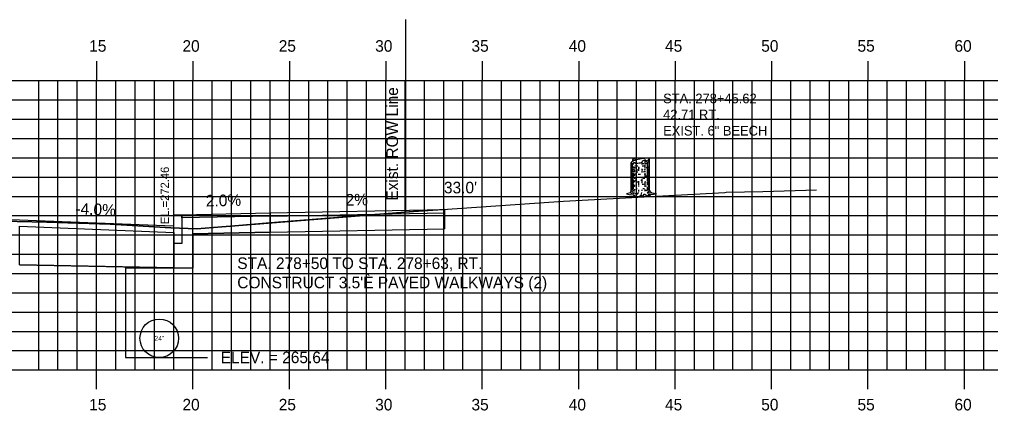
# Model space of a CAD drawing. Extents: x 854676 to 854846, y 366268 to 366378.
# Drawn here: x 854770.1 to 854820.5, y 366300.1 to 366320.4 of the extents above; entities that cross this region are included whole.
import ezdxf

# ---------------------------------------------------------------- set-up
doc = ezdxf.new("R2010")
doc.units = 0
for name, color, linetype in [('ANNOTATION', 7, 'Continuous'), ('D_Curb_Type_1_Rt', 7, 'Continuous'), ('D_Roadway_Edge_Shoulder', 7, 'Continuous'), ('D_Roadway_Sidewalks_Paved', 7, 'Continuous'), ('D_Roadway_SubGrade', 7, 'Continuous'), ('D_Text_Monospaced', 7, 'Continuous'), ('D_Text_Standard', 7, 'Continuous'), ('E_ROW_Line', 7, 'Continuous'), ('H_V ANNOTATION', 7, 'Continuous'), ('JUNK COM EXC', 7, 'Continuous'), ('junk strct exc', 7, 'Continuous'), ('MAJOR', 7, 'Continuous'), ('MINOR', 7, 'Continuous'), ('PDRAIN', 7, 'Continuous'), ('S_Roadway_Centerline', 7, 'Continuous'), ('S_Trees_Decid_NonPay', 7, 'Continuous')]:
    doc.layers.add(name, color=color, linetype=linetype)

msp = doc.modelspace()

# ---------------------------------------------------------------- linework, layer by layer
at = {"layer": 'D_Curb_Type_1_Rt'}
msp.add_lwpolyline([(854778.523, 366310.284), (854778.523, 366308.784), (854778.106, 366308.784), (854778.106, 366310.284)], close=True, dxfattribs=at)
at = {"layer": 'D_Roadway_Edge_Shoulder'}
msp.add_lwpolyline([(854740.106, 366309.92), (854748.106, 366310.24), (854759.106, 366310.24), (854770.106, 366310.02), (854778.103, 366309.701)], dxfattribs=at)
at = {"layer": 'D_Roadway_Sidewalks_Paved'}
msp.add_line((854783.115, 366310.209), (854792.151, 366310.39), dxfattribs=at)
msp.add_lwpolyline([(854783.111, 366310.375), (854792.151, 366310.556)], dxfattribs=at)
msp.add_lwpolyline([(854778.523, 366310.283), (854783.111, 366310.375), (854783.111, 366310.208), (854778.523, 366310.116)], close=True, dxfattribs=at)
at = {"layer": 'D_Roadway_SubGrade'}
for p in [(854792.151, 366310.556), (854783.112, 366309.375)]:
    msp.add_line(p, (854792.151, 366309.556), dxfattribs=at)
msp.add_lwpolyline([(854783.112, 366310.208), (854783.112, 366309.375), (854779.106, 366309.295), (854779.106, 366307.507), (854778.106, 366307.527)], dxfattribs=at)
msp.add_lwpolyline([(854770.106, 366309.687), (854778.106, 366309.367), (854778.106, 366307.527), (854770.106, 366307.687)], close=True, dxfattribs=at)
at = {"layer": 'D_Text_Standard'}
msp.add_lwpolyline([(854779.106, 366302.876), (854779.182, 366302.886), (854779.862, 366302.886)], dxfattribs=at)
at = {"layer": 'E_ROW_Line'}
msp.add_line((854790.137, 366310.411), (854790.137, 366320.411), dxfattribs=at)
at = {"layer": 'JUNK COM EXC'}
for points in [[(854783.112, 366309.858), (854783.112, 366309.375), (854792.151, 366309.556), (854792.151, 366310.556), (854790.546, 366310.443), (854783.112, 366309.858)], [(854770.106, 366307.687), (854779.106, 366307.507), (854779.106, 366309.295), (854783.112, 366309.375), (854783.111, 366309.858), (854781.269, 366309.713), (854780.594, 366309.653), (854779.299, 366309.553), (854777.965, 366309.609), (854774.811, 366309.794), (854771.526, 366309.892), (854768.432, 366309.965)]]:
    msp.add_lwpolyline(points, dxfattribs=at)
at = {"layer": 'junk strct exc'}
msp.add_lwpolyline([(854775.606, 366307.507), (854775.606, 366302.876), (854779.106, 366302.876), (854779.106, 366307.507)], close=True, dxfattribs=at)
at = {"layer": 'MAJOR'}
for p, q in [((854774.106, 366318.238), (854774.106, 366317.236)), ((854779.106, 366318.238), (854779.106, 366317.236)), ((854784.106, 366318.238), (854784.106, 366317.236)), ((854789.106, 366318.238), (854789.106, 366317.236)), ((854794.106, 366318.238), (854794.106, 366317.236)), ((854799.106, 366318.238), (854799.106, 366317.236)), ((854804.106, 366318.238), (854804.106, 366317.236)), ((854809.106, 366318.238), (854809.106, 366317.236)), ((854814.106, 366318.238), (854814.106, 366317.236)), ((854819.106, 366318.238), (854819.106, 366317.236)), ((854689.106, 366317.236), (854829.106, 366317.236)), ((854689.106, 366317.236), (854829.106, 366317.236)), ((854774.106, 366302.236), (854774.106, 366317.236)), ((854779.106, 366302.236), (854779.106, 366317.236)), ((854784.106, 366302.236), (854784.106, 366317.236)), ((854789.106, 366302.236), (854789.106, 366317.236)), ((854794.106, 366302.236), (854794.106, 366317.236)), ((854799.106, 366302.236), (854799.106, 366317.236)), ((854804.106, 366302.236), (854804.106, 366317.236)), ((854809.106, 366302.236), (854809.106, 366317.236)), ((854814.106, 366302.236), (854814.106, 366317.236)), ((854819.106, 366302.236), (854819.106, 366317.236)), ((854689.106, 366312.236), (854829.106, 366312.236)), ((854689.106, 366307.236), (854829.106, 366307.236)), ((854689.106, 366302.236), (854829.106, 366302.236)), ((854689.106, 366302.236), (854829.106, 366302.236)), ((854774.106, 366301.234), (854774.106, 366302.236)), ((854779.106, 366301.234), (854779.106, 366302.236)), ((854784.106, 366301.234), (854784.106, 366302.236)), ((854789.106, 366301.234), (854789.106, 366302.236)), ((854794.106, 366301.234), (854794.106, 366302.236)), ((854799.106, 366301.234), (854799.106, 366302.236)), ((854804.106, 366301.234), (854804.106, 366302.236)), ((854809.106, 366301.234), (854809.106, 366302.236)), ((854814.106, 366301.234), (854814.106, 366302.236)), ((854819.106, 366301.234), (854819.106, 366302.236))]:
    msp.add_line(p, q, dxfattribs=at)
at = {"layer": 'MINOR'}
for p, q in [((854771.106, 366302.236), (854771.106, 366317.236)), ((854772.106, 366302.236), (854772.106, 366317.236)), ((854773.106, 366302.236), (854773.106, 366317.236)), ((854775.106, 366302.236), (854775.106, 366317.236)), ((854776.106, 366302.236), (854776.106, 366317.236)), ((854777.106, 366302.236), (854777.106, 366317.236)), ((854778.106, 366302.236), (854778.106, 366317.236)), ((854780.106, 366302.236), (854780.106, 366317.236)), ((854781.106, 366302.236), (854781.106, 366317.236)), ((854782.106, 366302.236), (854782.106, 366317.236)), ((854783.106, 366302.236), (854783.106, 366317.236)), ((854785.106, 366302.236), (854785.106, 366317.236)), ((854786.106, 366302.236), (854786.106, 366317.236)), ((854787.106, 366302.236), (854787.106, 366317.236)), ((854788.106, 366302.236), (854788.106, 366317.236)), ((854790.106, 366302.236), (854790.106, 366317.236)), ((854791.106, 366302.236), (854791.106, 366317.236)), ((854792.106, 366302.236), (854792.106, 366317.236)), ((854793.106, 366302.236), (854793.106, 366317.236)), ((854795.106, 366302.236), (854795.106, 366317.236)), ((854796.106, 366302.236), (854796.106, 366317.236)), ((854797.106, 366302.236), (854797.106, 366317.236)), ((854798.106, 366302.236), (854798.106, 366317.236)), ((854800.106, 366302.236), (854800.106, 366317.236)), ((854801.106, 366302.236), (854801.106, 366317.236)), ((854802.106, 366302.236), (854802.106, 366317.236)), ((854803.106, 366302.236), (854803.106, 366317.236)), ((854805.106, 366302.236), (854805.106, 366317.236)), ((854806.106, 366302.236), (854806.106, 366317.236)), ((854807.106, 366302.236), (854807.106, 366317.236)), ((854808.106, 366302.236), (854808.106, 366317.236)), ((854810.106, 366302.236), (854810.106, 366317.236)), ((854811.106, 366302.236), (854811.106, 366317.236)), ((854812.106, 366302.236), (854812.106, 366317.236)), ((854813.106, 366302.236), (854813.106, 366317.236)), ((854815.106, 366302.236), (854815.106, 366317.236)), ((854816.106, 366302.236), (854816.106, 366317.236)), ((854817.106, 366302.236), (854817.106, 366317.236)), ((854818.106, 366302.236), (854818.106, 366317.236)), ((854820.106, 366302.236), (854820.106, 366317.236)), ((854689.106, 366316.236), (854829.106, 366316.236)), ((854689.106, 366315.236), (854829.106, 366315.236)), ((854689.106, 366314.236), (854829.106, 366314.236)), ((854689.106, 366313.236), (854829.106, 366313.236)), ((854689.106, 366311.236), (854829.106, 366311.236)), ((854689.106, 366310.236), (854829.106, 366310.236)), ((854689.106, 366309.236), (854829.106, 366309.236)), ((854689.106, 366308.236), (854829.106, 366308.236)), ((854689.106, 366306.236), (854829.106, 366306.236)), ((854689.106, 366305.236), (854829.106, 366305.236)), ((854689.106, 366304.236), (854829.106, 366304.236)), ((854689.106, 366303.236), (854829.106, 366303.236))]:
    msp.add_line(p, q, dxfattribs=at)
at = {"layer": 'PDRAIN'}
msp.add_lwpolyline([(854775.606, 366307.577), (854775.606, 366302.876), (854779.106, 366302.876), (854779.106, 366307.507)], dxfattribs=at)
msp.add_circle((854777.356, 366303.876), 1, dxfattribs=at)
at = {"layer": 'S_Roadway_Centerline'}
msp.add_lwpolyline([(854768.432, 366309.965), (854771.526, 366309.892), (854774.811, 366309.794), (854777.965, 366309.609), (854779.299, 366309.553), (854780.594, 366309.653), (854781.269, 366309.713), (854790.546, 366310.443), (854798.319, 366310.991), (854806.682, 366311.444), (854806.754, 366311.454), (854808.651, 366311.486), (854811.433, 366311.566)], dxfattribs=at)
at = {"layer": 'S_Trees_Decid_NonPay'}
for p, q in [((854801.886, 366312.941), (854801.886, 366312.723)), ((854801.928, 366312.936), (854801.928, 366312.884)), ((854802.086, 366312.946), (854802.086, 366312.867)), ((854802.383, 366312.999), (854802.383, 366312.892)), ((854802.53, 366313.044), (854802.53, 366312.896)), ((854802.649, 366313.027), (854802.649, 366312.727)), ((854802.717, 366313.114), (854802.717, 366313.02)), ((854801.859, 366312.871), (854801.859, 366312.789)), ((854801.859, 366312.719), (854801.859, 366312.589)), ((854801.859, 366312.567), (854801.859, 366312.385)), ((854801.886, 366312.654), (854801.886, 366312.502)), ((854801.928, 366312.781), (854801.928, 366312.698)), ((854801.928, 366312.663), (854801.928, 366312.589)), ((854801.928, 366312.562), (854801.928, 366312.502)), ((854801.928, 366312.449), (854801.928, 366312.268)), ((854801.999, 366312.762), (854801.999, 366312.676)), ((854801.999, 366312.605), (854801.999, 366312.484)), ((854801.999, 366312.409), (854801.999, 366312.294)), ((854802.086, 366312.781), (854802.086, 366312.696)), ((854802.086, 366312.585), (854802.086, 366312.484)), ((854802.203, 366312.762), (854802.203, 366312.562)), ((854802.383, 366312.663), (854802.383, 366312.577)), ((854802.383, 366312.542), (854802.383, 366312.472)), ((854802.53, 366312.848), (854802.53, 366312.68)), ((854802.649, 366312.698), (854802.649, 366312.567)), ((854802.649, 366312.533), (854802.649, 366312.252)), ((854802.717, 366312.793), (854802.717, 366312.71)), ((854802.717, 366312.641), (854802.717, 366312.39)), ((854801.857, 366311.924), (854801.858, 366311.665)), ((854801.859, 366312.338), (854801.859, 366312.091)), ((854801.859, 366312.072), (854801.859, 366311.978)), ((854801.886, 366312.397), (854801.886, 366312.319)), ((854801.886, 366312.293), (854801.886, 366312.186)), ((854801.886, 366312.151), (854801.886, 366312.05)), ((854801.886, 366312.024), (854801.886, 366311.842)), ((854801.928, 366312.237), (854801.928, 366312.155)), ((854801.928, 366312.101), (854801.928, 366311.93)), ((854801.928, 366311.897), (854801.928, 366311.617)), ((854801.999, 366312.233), (854801.999, 366312.151)), ((854801.999, 366312.064), (854801.999, 366311.967)), ((854802.086, 366312.399), (854802.086, 366312.323)), ((854802.086, 366312.138), (854802.086, 366312.041)), ((854802.203, 366312.025), (854802.203, 366311.838)), ((854802.383, 366312.138), (854802.383, 366311.916)), ((854802.53, 366312.373), (854802.53, 366312.225)), ((854802.53, 366311.955), (854802.53, 366311.802)), ((854802.649, 366312.182), (854802.649, 366312.037)), ((854802.649, 366311.967), (854802.649, 366311.825)), ((854802.717, 366312.307), (854802.717, 366312.077)), ((854802.717, 366312.006), (854802.717, 366311.846)), ((854801.806, 366311.378), (854801.873, 366311.409)), ((854801.888, 366311.5), (854801.853, 366311.449)), ((854801.859, 366311.626), (854801.859, 366311.552)), ((854801.886, 366311.739), (854801.886, 366311.547)), ((854801.928, 366311.565), (854801.928, 366311.539)), ((854801.999, 366311.838), (854801.999, 366311.739)), ((854801.999, 366311.609), (854801.999, 366311.551)), ((854802.086, 366311.716), (854802.086, 366311.492)), ((854802.203, 366311.807), (854802.203, 366311.754)), ((854802.203, 366311.578), (854802.203, 366311.487)), ((854802.343, 366311.296), (854802.378, 366311.442)), ((854802.383, 366311.583), (854802.383, 366311.516)), ((854802.53, 366311.59), (854802.53, 366311.512)), ((854802.649, 366311.724), (854802.649, 366311.543)), ((854802.649, 366311.483), (854802.691, 366311.387)), ((854802.717, 366311.829), (854802.717, 366311.724)), ((854802.717, 366311.688), (854802.717, 366311.564))]:
    msp.add_line(p, q, dxfattribs=at)
for points in [[(854801.817, 366312.978), (854801.817, 366311.566), (854801.795, 366311.418), (854801.592, 366311.375), (854801.731, 366311.339), (854801.95, 366311.321), (854802.019, 366311.277), (854801.898, 366311.189), (854802.229, 366311.232), (854802.343, 366311.296), (854802.435, 366311.236), (854802.491, 366311.315), (854802.483, 366311.352), (854802.544, 366311.354), (854802.596, 366311.296), (854802.828, 366311.245), (854802.701, 366311.333), (854802.833, 366311.335), (854803.141, 366311.373), (854802.903, 366311.403), (854802.825, 366311.461), (854802.786, 366311.583), (854802.769, 366311.936), (854802.769, 366313.17)], [(854801.912, 366313.059), (854801.916, 366313.153), (854801.931, 366313.126), (854801.931, 366313.248), (854801.952, 366313.184), (854801.966, 366313.217), (854801.983, 366313.161), (854801.999, 366313.178), (854802.017, 366313.17), (854802.036, 366313.103)], [(854801.935, 366312.935), (854801.952, 366312.997), (854801.974, 366312.985), (854802.005, 366313.02), (854802.038, 366312.941)], [(854802.405, 366313.004), (854802.413, 366313.071), (854802.437, 366313.075), (854802.446, 366313.11), (854802.477, 366313.096), (854802.491, 366313.11), (854802.515, 366313.087), (854802.538, 366313.096), (854802.551, 366313.145), (854802.559, 366313.102), (854802.59, 366313.11), (854802.593, 366313.059)], [(854801.857, 366311.426), (854801.935, 366311.409), (854801.952, 366311.366)], [(854801.935, 366311.409), (854801.979, 366311.444), (854801.987, 366311.492)], [(854802.083, 366311.444), (854802.077, 366311.375), (854802.014, 366311.362)], [(854802.195, 366311.438), (854802.195, 366311.401), (854802.143, 366311.371), (854802.126, 366311.321)], [(854802.72, 366311.521), (854802.728, 366311.444), (854802.806, 366311.395)]]:
    msp.add_lwpolyline(points, dxfattribs=at)
for centre, radius, start, end in [((854801.841, 366312.978), 0.0237, 161.8277, 175.7722), ((854801.836, 366312.978), 0.0179, 175.7722, 191.8277), ((854801.836, 366312.978), 0.0179, 191.8277, 207.8832), ((854801.837, 366312.909), 0.0191, 173.8872, 180), ((854801.837, 366312.909), 0.0191, 180, 196.0515), ((854801.851, 366312.975), 0.0336, 143.0514, 161.8277), ((854801.843, 366312.911), 0.0252, 196.0515, 210), ((854801.841, 366312.981), 0.0237, 207.8832, 221.8277), ((854801.848, 366312.988), 0.0336, 221.8277, 240.604), ((854801.899, 366312.939), 0.0935, 131.8277, 143.0514), ((854801.877, 366313.04), 0.0935, 240.604, 251.8277), ((854802.051, 366312.769), 0.322, 109.7098, 131.8277), ((854801.949, 366313.257), 0.322, 251.8277, 267.5521), ((854802.788, 366310.711), 2.507, 101.8277, 109.7098), ((854801.798, 366315.437), 2.507, 275.4987, 281.8277), ((854802.788, 366310.711), 2.507, 93.9457, 101.8277), ((854801.798, 366315.437), 2.507, 281.8277, 284.0013), ((854802.294, 366315.284), 2.356, 272.1614, 274.76), ((854802.294, 366315.284), 2.356, 276.7201, 278.1032), ((854801.798, 366315.437), 2.507, 288.4719, 289.7098), ((854802.637, 366312.891), 0.322, 71.8277, 93.9457), ((854802.58, 366313.274), 0.326, 278.1032, 282.1964), ((854802.535, 366313.38), 0.322, 289.7098, 311.8277), ((854802.58, 366313.274), 0.326, 291.6757, 300), ((854802.709, 366313.108), 0.0935, 60.604, 71.8277), ((854802.694, 366313.077), 0.0984, 300, 311.2506), ((854802.688, 366313.209), 0.0935, 311.8277, 323.0514), ((854802.738, 366313.161), 0.0336, 41.8277, 60.604), ((854802.735, 366313.029), 0.0356, 311.2506, 330), ((854802.735, 366313.173), 0.0336, 323.0514, 341.8277), ((854802.745, 366313.167), 0.0237, 27.8832, 41.8277), ((854802.751, 366313.17), 0.0179, 11.8277, 27.8832), ((854802.744, 366313.024), 0.0252, 330, 343.9485), ((854802.745, 366313.17), 0.0237, 341.8277, 355.7722), ((854802.751, 366313.17), 0.0179, 355.7722, 11.8277), ((854802.75, 366313.022), 0.0191, 0, 16.0515), ((854802.75, 366313.022), 0.0191, 343.9485, 0), ((854801.837, 366312.808), 0.0191, 173.8872, 180), ((854801.837, 366312.808), 0.0191, 180, 196.0515), ((854801.837, 366312.705), 0.0191, 173.8872, 180), ((854801.837, 366312.705), 0.0191, 180, 196.0515), ((854801.837, 366312.6), 0.0191, 173.8872, 180), ((854801.837, 366312.6), 0.0191, 180, 196.0515), ((854801.837, 366312.485), 0.0191, 173.8872, 180), ((854801.837, 366312.485), 0.0191, 180, 196.0515), ((854801.843, 366312.81), 0.0252, 196.0515, 210), ((854801.843, 366312.602), 0.0252, 196.0515, 210), ((854801.843, 366312.487), 0.0252, 196.0515, 210), ((854801.852, 366312.916), 0.0356, 210, 228.7494), ((854801.852, 366312.815), 0.0356, 210, 228.7494), ((854801.852, 366312.607), 0.0356, 210, 228.7494), ((854801.852, 366312.492), 0.0356, 210, 228.7494), ((854801.894, 366312.963), 0.0984, 228.7494, 240), ((854801.894, 366312.862), 0.0984, 228.7494, 240), ((854801.894, 366312.654), 0.0984, 228.7494, 240), ((854801.894, 366312.539), 0.0984, 228.7494, 240), ((854802.008, 366313.161), 0.326, 240, 248.0494), ((854802.008, 366313.06), 0.326, 240, 248.0494), ((854802.008, 366312.852), 0.326, 240, 248.0494), ((854802.008, 366312.737), 0.326, 240, 255.9618), ((854802.008, 366312.957), 0.326, 255.9618, 261.8968), ((854802.008, 366312.852), 0.326, 255.9618, 261.8968), ((854802.008, 366313.06), 0.326, 260.9146, 261.8968), ((854802.294, 366315.07), 2.356, 261.8968, 264.9353), ((854802.294, 366314.967), 2.356, 261.8968, 262.6162), ((854802.294, 366314.862), 2.356, 261.8968, 262.8132), ((854802.294, 366314.747), 2.356, 262.8132, 264.9353), ((854802.294, 366315.171), 2.356, 263.2266, 266.8519), ((854802.294, 366314.862), 2.356, 264.9353, 266.9933), ((854802.294, 366314.967), 2.356, 266.0259, 267.8019), ((854802.294, 366315.07), 2.356, 267.8019, 269.1881), ((854802.294, 366314.967), 2.356, 272.1614, 273.4964), ((854802.294, 366315.171), 2.356, 272.6327, 275.758), ((854802.294, 366314.862), 2.356, 274.3638, 276.7318), ((854802.294, 366314.967), 2.356, 275.0054, 276.6587), ((854802.294, 366314.747), 2.356, 275.2089, 277.3412), ((854802.294, 366315.07), 2.356, 277.4481, 278.1032), ((854802.58, 366313.06), 0.326, 278.1032, 289.5833), ((854802.58, 366313.161), 0.326, 282.1964, 299.0901), ((854802.58, 366312.957), 0.326, 282.1964, 288.3169), ((854802.58, 366312.852), 0.326, 282.1964, 294.8455), ((854802.58, 366312.737), 0.326, 294.8455, 300), ((854802.58, 366313.06), 0.326, 296.4281, 300), ((854802.58, 366312.957), 0.326, 296.757, 300), ((854802.694, 366312.862), 0.0984, 300, 311.2506), ((854802.694, 366312.76), 0.0984, 300, 311.2506), ((854802.694, 366312.539), 0.0984, 300, 311.2506), ((854802.735, 366312.815), 0.0356, 311.2506, 330), ((854802.735, 366312.712), 0.0356, 311.2506, 330), ((854802.735, 366312.492), 0.0356, 311.2506, 330), ((854802.744, 366312.81), 0.0252, 330, 343.9485), ((854802.744, 366312.707), 0.0252, 330, 343.9485), ((854802.744, 366312.487), 0.0252, 330, 343.9485), ((854802.75, 366312.808), 0.0191, 0, 16.0515), ((854802.75, 366312.808), 0.0191, 343.9485, 0), ((854802.75, 366312.705), 0.0191, 0, 16.0515), ((854802.75, 366312.705), 0.0191, 343.9485, 0), ((854802.75, 366312.485), 0.0191, 0, 16.0515), ((854802.75, 366312.485), 0.0191, 343.9485, 0), ((854801.837, 366312.371), 0.0191, 173.8872, 180), ((854801.837, 366312.371), 0.0191, 180, 196.0515), ((854801.843, 366312.373), 0.0252, 196.0515, 210), ((854801.837, 366312.166), 0.0191, 173.8872, 180), ((854801.837, 366312.166), 0.0191, 180, 196.0515), ((854801.837, 366312.075), 0.0191, 173.8872, 180), ((854801.843, 366312.168), 0.0252, 196.0515, 210), ((854801.852, 366312.378), 0.0356, 210, 228.7494), ((854801.84, 366312.271), 0.0191, 173.8872, 180), ((854801.84, 366312.271), 0.0191, 180, 196.0515), ((854801.846, 366312.272), 0.0252, 196.0515, 210), ((854801.852, 366312.173), 0.0356, 210, 228.7494), ((854801.855, 366312.278), 0.0356, 210, 228.7494), ((854801.893, 366312.425), 0.0984, 228.7494, 240), ((854801.894, 366312.22), 0.0984, 228.7494, 240), ((854801.896, 366312.325), 0.0984, 228.7494, 240), ((854802.007, 366312.622), 0.326, 240, 242.9942), ((854802.008, 366312.417), 0.326, 240, 242.8475), ((854802.01, 366312.522), 0.326, 240, 247.5951), ((854802.007, 366312.622), 0.326, 248.1902, 256.0964), ((854802.008, 366312.417), 0.326, 248.0494, 255.9618), ((854802.008, 366312.213), 0.326, 248.0494, 255.9618), ((854802.296, 366314.532), 2.356, 262.7545, 265.0266), ((854802.294, 366314.427), 2.356, 263.572, 264.9353), ((854802.294, 366314.337), 2.356, 264.7274, 267.8019), ((854802.294, 366314.747), 2.356, 267.586, 270), ((854802.294, 366314.747), 2.356, 270, 270.4422), ((854802.294, 366314.427), 2.356, 270.9946, 272.1614), ((854802.296, 366314.532), 2.356, 273.1471, 275.6557), ((854802.294, 366314.337), 2.356, 275.5135, 277.4157), ((854802.293, 366314.632), 2.356, 277.1385, 278.1032), ((854802.579, 366312.622), 0.326, 278.1032, 282.3301), ((854802.582, 366312.522), 0.326, 283.0921, 300), ((854802.58, 366312.327), 0.326, 286.0817, 298.061), ((854802.579, 366312.622), 0.326, 292.1344, 300), ((854802.58, 366312.417), 0.326, 294.8455, 300), ((854802.693, 366312.425), 0.0984, 300, 311.2506), ((854802.694, 366312.22), 0.0984, 300, 311.2506), ((854802.734, 366312.378), 0.0356, 311.2506, 330), ((854802.735, 366312.173), 0.0356, 311.2506, 330), ((854802.744, 366312.373), 0.0252, 330, 343.9485), ((854802.744, 366312.168), 0.0252, 330, 343.9485), ((854802.749, 366312.371), 0.0191, 0, 16.0515), ((854802.749, 366312.371), 0.0191, 343.9485, 0), ((854802.75, 366312.166), 0.0191, 0, 16.0515), ((854802.75, 366312.166), 0.0191, 343.9485, 0), ((854802.753, 366312.271), 0.0191, 0, 16.0515), ((854801.841, 366311.847), 0.0191, 173.8872, 180), ((854801.841, 366311.847), 0.0191, 180, 196.0515), ((854801.847, 366311.849), 0.0252, 196.0515, 210), ((854801.856, 366311.854), 0.0356, 210, 228.7494), ((854801.898, 366311.901), 0.0984, 228.7494, 240), ((854801.852, 366311.626), 0.0191, 173.8872, 180), ((854801.852, 366311.626), 0.0191, 180, 196.0515), ((854801.858, 366311.628), 0.0252, 196.0515, 210), ((854801.867, 366311.633), 0.0356, 210, 228.7494), ((854801.908, 366311.68), 0.0984, 228.7494, 240), ((854802.017, 366311.988), 0.326, 240, 246.3456), ((854802.022, 366311.877), 0.326, 245.2906, 261.8968), ((854802.012, 366312.098), 0.326, 255.2259, 261.8968), ((854802.298, 366314.108), 2.356, 261.8968, 262.7137), ((854802.308, 366313.887), 2.356, 261.8968, 262.4597), ((854802.303, 366313.998), 2.356, 264.7171, 265.8136), ((854802.308, 366313.887), 2.356, 264.5833, 265.4449), ((854802.294, 366314.223), 2.356, 272.531, 275.758), ((854802.303, 366313.998), 2.356, 273.1842, 275.0911), ((854802.298, 366314.108), 2.356, 275.5148, 277.7774), ((854802.308, 366313.887), 2.356, 276.4667, 278.1032), ((854802.594, 366311.877), 0.326, 278.1032, 279.6166), ((854802.584, 366312.098), 0.326, 294.0625, 300), ((854802.594, 366311.877), 0.326, 292.0839, 300), ((854802.589, 366311.988), 0.326, 298.0903, 300), ((854802.698, 366311.901), 0.0984, 300, 311.2506), ((854802.703, 366311.79), 0.0984, 300, 311.2506), ((854802.708, 366311.68), 0.0984, 300, 311.2506), ((854802.739, 366311.854), 0.0356, 311.2506, 330), ((854802.744, 366311.743), 0.0356, 311.2506, 330), ((854802.748, 366311.849), 0.0252, 330, 343.9485), ((854802.754, 366311.847), 0.0191, 0, 16.0515), ((854802.754, 366311.847), 0.0191, 343.9485, 0), ((854802.75, 366311.633), 0.0356, 311.2506, 330), ((854802.753, 366311.738), 0.0252, 330, 343.9485), ((854802.759, 366311.736), 0.0191, 0, 16.0515), ((854802.759, 366311.736), 0.0191, 343.9485, 0), ((854802.759, 366311.628), 0.0252, 330, 343.9485), ((854802.765, 366311.626), 0.0191, 0, 16.0515), ((854802.765, 366311.626), 0.0191, 343.9485, 0)]:
    msp.add_arc(centre, radius, start, end, dxfattribs=at)

# ---------------------------------------------------------------- texts
at = {"layer": 'ANNOTATION'}
for s, rotation, p in [('2.0%', 1.1485, (854779.779, 366310.709)), ('2%', 1.1462, (854787.026, 366310.754)), ('-4.0%', 357.7093, (854773.001, 366310.306))]:
    msp.add_text(s, height=0.6, rotation=rotation, dxfattribs=at).set_placement(p)
for s, p in [('STA. 278+50 TO STA. 278+63, RT.', (854781.403, 366307.468)), ("CONSTRUCT 3.5'È PAVED WALKWAYS (2)", (854781.403, 366306.468))]:
    msp.add_text(s, height=0.6, dxfattribs=at).set_placement(p)
at = {"layer": 'D_Text_Monospaced'}
for s, height, p in [('STA. 278+45.62', 0.49998, (854803.484, 366316.064)), ('42.71 RT.', 0.5, (854803.484, 366315.23)), ('EXIST. 6" BEECH', 0.49998, (854803.484, 366314.39))]:
    msp.add_text(s, height=height, dxfattribs=at).set_placement(p)
at = {"layer": 'D_Text_Standard'}
msp.add_text(' EL.=272.46', height=0.4335, rotation=90, dxfattribs=at).set_placement((854777.861, 366309.631))
for s, p in [("33.0'", (854792.119, 366311.392)), ('ELEV. = 265.64', (854780.542, 366302.586))]:
    msp.add_text(s, height=0.6, dxfattribs=at).set_placement(p)
at = {"layer": 'E_ROW_Line'}
msp.add_text('Exist. ROW Line', height=0.6, rotation=90, dxfattribs=at).set_placement((854789.737, 366311.011))
at = {"layer": 'H_V ANNOTATION'}
for s, p in [('15', (854773.724, 366318.736)), ('20', (854778.56, 366318.736)), ('25', (854783.552, 366318.736)), ('30', (854788.555, 366318.736)), ('35', (854793.547, 366318.736)), ('40', (854798.592, 366318.736)), ('45', (854803.584, 366318.736)), ('50', (854808.571, 366318.736)), ('55', (854813.563, 366318.736)), ('60', (854818.592, 366318.736)), ('15', (854773.724, 366300.136)), ('20', (854778.56, 366300.136)), ('25', (854783.552, 366300.136)), ('30', (854788.555, 366300.136)), ('35', (854793.547, 366300.136)), ('40', (854798.592, 366300.136)), ('45', (854803.584, 366300.136)), ('50', (854808.571, 366300.136)), ('55', (854813.563, 366300.136)), ('60', (854818.592, 366300.136))]:
    msp.add_text(s, height=0.6, dxfattribs=at).set_placement(p)
at = {"layer": 'PDRAIN'}
msp.add_text('24"', height=0.25, dxfattribs=at).set_placement((854777.114, 366303.751))

doc.saveas('drawing.dxf')
